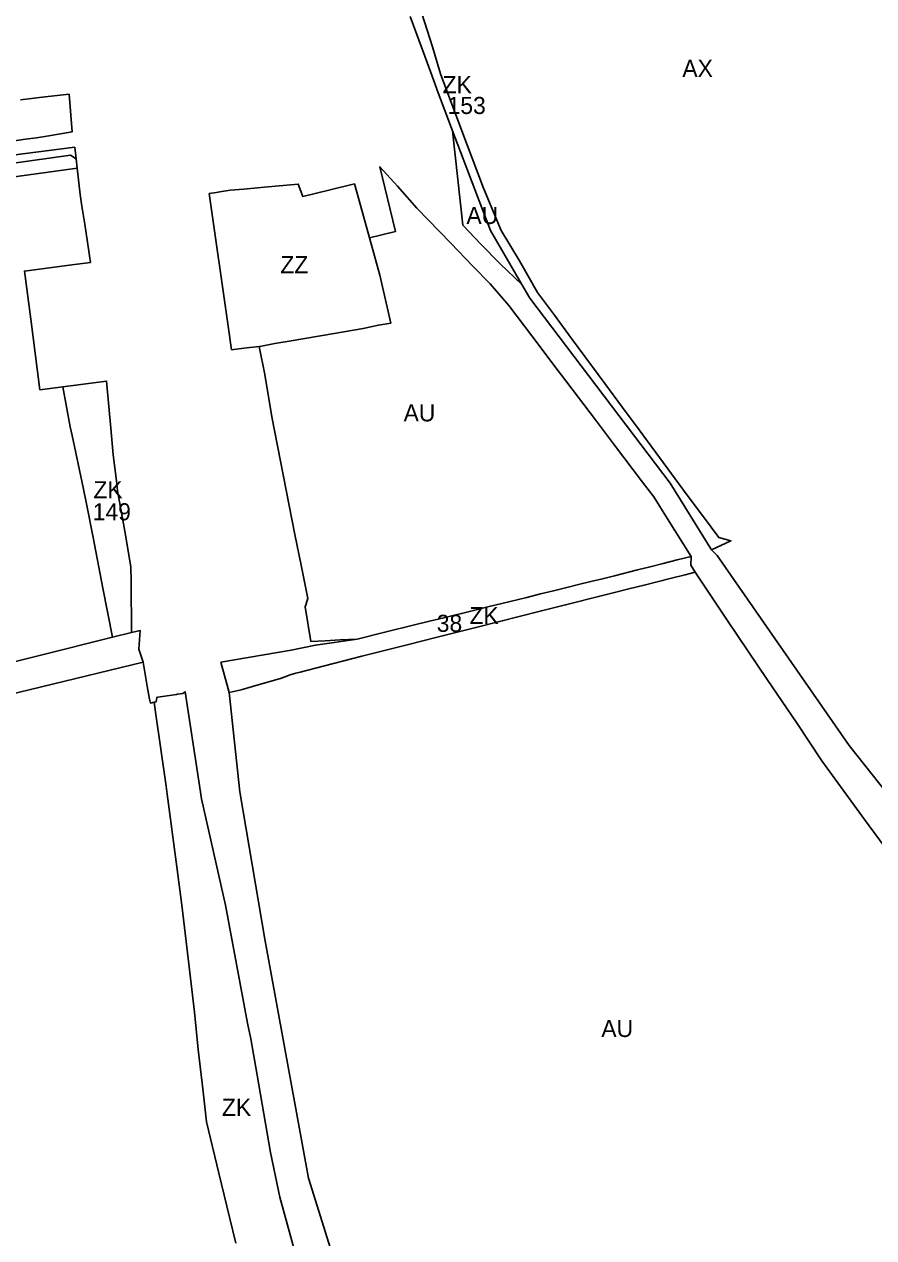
# Model space of a CAD drawing. Extents: x -521939 to -516426, y -1197857 to -1189551.
# Drawn here: x -519323 to -518826, y -1192859 to -1192149 of the extents above; entities that cross this region are included whole.
import ezdxf

# ---------------------------------------------------------------- set-up
doc = ezdxf.new("R2010")
doc.units = 0
for name, color, linetype in [('90640013', 7, 'Continuous'), ('90670013', 7, 'Continuous'), ('90710013', 7, 'Continuous'), ('90710023', 7, 'Continuous'), ('90750013', 7, 'Continuous'), ('90760013', 7, 'Continuous'), ('ID_navrh', 7, 'Continuous')]:
    doc.layers.add(name, color=color, linetype=linetype)

msp = doc.modelspace()

# ---------------------------------------------------------------- linework, layer by layer
at = {"layer": '90640013'}
msp.add_lwpolyline([(-519293.15, -1192221.23), (-519385.99, -1192233.14), (-519458.84, -1192240.98), (-519478.96, -1192243.26), (-519486.4, -1192244.11), (-519538.54, -1192250.02), (-519608.83, -1192258.36), (-519670.99, -1192265.56), (-519670.87, -1192266.69), (-519670.1, -1192273.68), (-519660.91, -1192268.23), (-519608.82, -1192261.75), (-519538.31, -1192254.24), (-519485.83, -1192249.1), (-519482.85, -1192248.8), (-519478.37, -1192248.37), (-519457.41, -1192246.31), (-519414.35, -1192241.81), (-519386.04, -1192238.58), (-519295.56, -1192225.98), (-519292.39, -1192228.11), (-519293.15, -1192221.23)], dxfattribs=at)
at = {"layer": '90670013'}
for points in [[(-519334.91, -1192218.48), (-519322.01, -1192216.62), (-519315.51, -1192215.67), (-519309.5, -1192214.8), (-519294.58, -1192212.21), (-519296.37, -1192190.24)], [(-519296.37, -1192190.24), (-519312.21, -1192192.03), (-519318.4, -1192192.73), (-519324.93, -1192193.46)], [(-519129.41, -1192242.66), (-519144.59, -1192246.35), (-519159.77, -1192250.04), (-519162.39, -1192242.78), (-519182.27, -1192244.61), (-519186.2, -1192244.97), (-519194.24, -1192245.71), (-519202.16, -1192246.44), (-519208.32, -1192247.41), (-519210.17, -1192247.71), (-519214.49, -1192248.39), (-519203.38, -1192325.77), (-519201.39, -1192339.64), (-519194.23, -1192338.74), (-519185.2, -1192337.66), (-519183.95, -1192337.51), (-519176.01, -1192336.03), (-519167.69, -1192334.62), (-519141.44, -1192330.1), (-519124.49, -1192327.18), (-519115.46, -1192325.17), (-519108.18, -1192324.09), (-519114.73, -1192296.08), (-519120.71, -1192274.22), (-519126.69, -1192252.35), (-519129.41, -1192242.66)]]:
    msp.add_lwpolyline(points, dxfattribs=at)
at = {"layer": '90710013'}
for points in [[(-519271.05, -1192507.61), (-519443.57, -1192550.97)], [(-519372.23, -1192551.03), (-519253.11, -1192522.25), (-519255.72, -1192514.6), (-519254.84, -1192503.78), (-519260.01, -1192504.83), (-519271.05, -1192507.61)], [(-519164.09, -1192868.23), (-519173.07, -1192834.93), (-519178.57, -1192808.82), (-519186.41, -1192763.61), (-519190.11, -1192742.39), (-519192.03, -1192733.27), (-519205.04, -1192664.2), (-519218.96, -1192602.21), (-519220.59, -1192591.78), (-519228.6, -1192539.54), (-519229.85, -1192540.57), (-519233.01, -1192541.03), (-519233.52, -1192541.1), (-519244.62, -1192542.72), (-519245.21, -1192542.95), (-519245.6, -1192545.49), (-519246.64, -1192545.7), (-519245.81, -1192551.56), (-519239.7, -1192594.73), (-519239.08, -1192599.36), (-519233.4, -1192641.79), (-519230.4, -1192664.21), (-519227.87, -1192685.59), (-519225.48, -1192707.05), (-519223.15, -1192726.84), (-519220.92, -1192748.67), (-519218.26, -1192771.67), (-519216.11, -1192790.93), (-519214.93, -1192795.79), (-519208.82, -1192820.97), (-519202.59, -1192846.65), (-519198.9, -1192861.88)]]:
    msp.add_lwpolyline(points, dxfattribs=at)
at = {"layer": '90710023'}
for points in [[(-519096.85, -1192144.75), (-519088.41, -1192167.96), (-519084.92, -1192177.56), (-519080.59, -1192189.45), (-519072.1, -1192211.71)], [(-519072.1, -1192211.71), (-519059.06, -1192245.89), (-519049.87, -1192269.96), (-519045.63, -1192277.25), (-519031.55, -1192301.49), (-519026.95, -1192309.4), (-518944.8, -1192417.71), (-518921.58, -1192455.03), (-518920.67, -1192456.5), (-518909.26, -1192451.23), (-518916.45, -1192449.41), (-518925.41, -1192437.29), (-518934.83, -1192424.56), (-518950.99, -1192402.69), (-518962.98, -1192386.51), (-518972.74, -1192373.31), (-518982.99, -1192359.44), (-519002.52, -1192333.06), (-519012.56, -1192319.48), (-519022.45, -1192306.15), (-519032.9, -1192287.75), (-519043.74, -1192269.98), (-519054.11, -1192245.13), (-519067.32, -1192210.12), (-519079.2, -1192178.33), (-519083.86, -1192162.62), (-519090.14, -1192143.06)], [(-519670.1, -1192273.68), (-519669.7, -1192277.39), (-519607.9, -1192269.69), (-519537.49, -1192262.2), (-519484.92, -1192257.05), (-519481.94, -1192256.7), (-519477.47, -1192256.17), (-519456.62, -1192254.15), (-519413.5, -1192249.64), (-519385.05, -1192246.39), (-519291.8, -1192233.4), (-519292.39, -1192228.11), (-519295.56, -1192225.98), (-519386.04, -1192238.58), (-519414.35, -1192241.81), (-519457.41, -1192246.31), (-519478.37, -1192248.37), (-519482.85, -1192248.8), (-519485.83, -1192249.1), (-519538.31, -1192254.24), (-519608.82, -1192261.75), (-519660.91, -1192268.23), (-519670.1, -1192273.68)], [(-519271.05, -1192507.61), (-519260.01, -1192504.83), (-519260.21, -1192475.38), (-519260.27, -1192466.51), (-519263.91, -1192445.66), (-519268.03, -1192422.01), (-519268.72, -1192416.34), (-519270.57, -1192401.05), (-519272, -1192385.55), (-519274.55, -1192357.98), (-519300.09, -1192361.31), (-519295.76, -1192384.75), (-519294.71, -1192389.71), (-519288.26, -1192420.08), (-519286.2, -1192429.76), (-519282.36, -1192449.47), (-519276.62, -1192479), (-519271.05, -1192507.61)], [(-519207.76, -1192522.22), (-519202.8, -1192540.04), (-519195.88, -1192538.48), (-519185.81, -1192535.58), (-519172.77, -1192531.87), (-519167.2, -1192529.66), (-519163.86, -1192528.76), (-519161.28, -1192528.12), (-519152.38, -1192525.82), (-519125.24, -1192518.78), (-519097.19, -1192511.77), (-519090.36, -1192509.99), (-519081.2, -1192507.68), (-519060.87, -1192502.57), (-519043.04, -1192498.09), (-519033.96, -1192495.77), (-519020.11, -1192492.23), (-519006, -1192488.76), (-518985.24, -1192483.53), (-518977.46, -1192481.59), (-518969.05, -1192479.46), (-518960.05, -1192477.14), (-518952.49, -1192475.3), (-518944.06, -1192473.16), (-518936.14, -1192471.19), (-518930.23, -1192469.72), (-518932.84, -1192465.6), (-518932.56, -1192460.45), (-518940.73, -1192462.51), (-518948.86, -1192464.56), (-518956.58, -1192466.5), (-518963.93, -1192468.35), (-518977.36, -1192471.72), (-518984.47, -1192473.47), (-518991.27, -1192475.14), (-518998.5, -1192476.92), (-519005.33, -1192478.6), (-519013.08, -1192480.51), (-519020.71, -1192482.38), (-519028.71, -1192484.35), (-519043.33, -1192487.95), (-519051.58, -1192489.98), (-519059.9, -1192492.02), (-519077.24, -1192496.29), (-519085.55, -1192498.33), (-519094.37, -1192500.5), (-519111.71, -1192504.77), (-519127.99, -1192508.77), (-519152.33, -1192512.23), (-519166.59, -1192515.29), (-519207.76, -1192522.22)]]:
    msp.add_lwpolyline(points, dxfattribs=at)
at = {"layer": '90750013'}
for points in [[(-519072.1, -1192211.71), (-519066.07, -1192266.75), (-519055.66, -1192277.84), (-519044.36, -1192289.47), (-519031.55, -1192301.49), (-519045.63, -1192277.25), (-519049.87, -1192269.96), (-519059.06, -1192245.89), (-519072.1, -1192211.71)], [(-518932.56, -1192460.45), (-518946.37, -1192438.53), (-518954.47, -1192425.68), (-518960.98, -1192417.09), (-518977.44, -1192395.36), (-518988.01, -1192381.41), (-519005.96, -1192357.71), (-519012.83, -1192348.64), (-519021.5, -1192337.2), (-519030.1, -1192325.84), (-519039.22, -1192313.8), (-519050.21, -1192301.17), (-519060.48, -1192290.5), (-519073.17, -1192277.32), (-519092.95, -1192256.78), (-519104.36, -1192244.08), (-519114.65, -1192232.63), (-519105.51, -1192270.55), (-519120.71, -1192274.22), (-519114.73, -1192296.08), (-519108.18, -1192324.09), (-519115.46, -1192325.17), (-519124.49, -1192327.18), (-519141.44, -1192330.1), (-519167.69, -1192334.62), (-519176.01, -1192336.03), (-519183.95, -1192337.51), (-519185.2, -1192337.66), (-519181.95, -1192354.19), (-519177.88, -1192378.92), (-519164.38, -1192447.68), (-519160.77, -1192465.6), (-519156.7, -1192485.01), (-519158.26, -1192489.84), (-519155.04, -1192510.13), (-519146.55, -1192509.71), (-519137.86, -1192509.27), (-519127.99, -1192508.77), (-519111.71, -1192504.77), (-519094.37, -1192500.5), (-519085.55, -1192498.33), (-519077.24, -1192496.29), (-519059.9, -1192492.02), (-519051.58, -1192489.98), (-519043.33, -1192487.95), (-519028.71, -1192484.35), (-519020.71, -1192482.38), (-519013.08, -1192480.51), (-519005.33, -1192478.6), (-518998.5, -1192476.92), (-518991.27, -1192475.14), (-518984.47, -1192473.47), (-518977.36, -1192471.72), (-518963.93, -1192468.35), (-518956.58, -1192466.5), (-518948.86, -1192464.56), (-518940.73, -1192462.51), (-518932.56, -1192460.45)], [(-518816.35, -1192634.29), (-518831.07, -1192614.22), (-518842.04, -1192599.23), (-518856.13, -1192579.88), (-518871, -1192557.6), (-518888.04, -1192532.35), (-518899.32, -1192515.59), (-518911.42, -1192497.6), (-518924.38, -1192478.48), (-518930.23, -1192469.72), (-518936.14, -1192471.19), (-518944.06, -1192473.16), (-518952.49, -1192475.3), (-518960.05, -1192477.14), (-518969.05, -1192479.46), (-518977.46, -1192481.59), (-518985.24, -1192483.53), (-519006, -1192488.76), (-519020.11, -1192492.23), (-519033.96, -1192495.77), (-519043.04, -1192498.09), (-519060.87, -1192502.57), (-519081.2, -1192507.68), (-519090.36, -1192509.99), (-519097.19, -1192511.77), (-519125.24, -1192518.78), (-519152.38, -1192525.82), (-519161.28, -1192528.12), (-519163.86, -1192528.76), (-519167.2, -1192529.66), (-519172.77, -1192531.87), (-519185.81, -1192535.58), (-519195.88, -1192538.48), (-519202.8, -1192540.04), (-519196.54, -1192598), (-519181.88, -1192684.13), (-519156.37, -1192823.91), (-519143.51, -1192865.04)]]:
    msp.add_lwpolyline(points, dxfattribs=at)
at = {"layer": '90760013'}
for points in [[(-519090.14, -1192143.06), (-519083.86, -1192162.62), (-519079.2, -1192178.33), (-519067.32, -1192210.12), (-519054.11, -1192245.13), (-519043.74, -1192269.98), (-519032.9, -1192287.75), (-519022.45, -1192306.15), (-519012.56, -1192319.48), (-519002.52, -1192333.06), (-518982.99, -1192359.44), (-518972.74, -1192373.31), (-518962.98, -1192386.51), (-518950.99, -1192402.69), (-518934.83, -1192424.56), (-518925.41, -1192437.29), (-518916.45, -1192449.41), (-518909.26, -1192451.23), (-518920.67, -1192456.5), (-518917.29, -1192459.81), (-518840.07, -1192570.95), (-518813.27, -1192604.88)], [(-519443.57, -1192550.97), (-519271.05, -1192507.61), (-519276.62, -1192479), (-519282.36, -1192449.47), (-519286.2, -1192429.76), (-519288.26, -1192420.08), (-519294.71, -1192389.71), (-519295.76, -1192384.75), (-519300.09, -1192361.31), (-519313.5, -1192363.06), (-519318.89, -1192321.77), (-519322.56, -1192293.65), (-519294.91, -1192290.05), (-519283.96, -1192288.62), (-519284.43, -1192284.69), (-519284.84, -1192282.04), (-519287.31, -1192266.22), (-519288.95, -1192255.73), (-519290, -1192248.98), (-519291.8, -1192233.4), (-519385.05, -1192246.39)], [(-519198.9, -1192861.88), (-519202.59, -1192846.65), (-519208.82, -1192820.97), (-519214.93, -1192795.79), (-519216.11, -1192790.93), (-519218.26, -1192771.67), (-519220.92, -1192748.67), (-519223.15, -1192726.84), (-519225.48, -1192707.05), (-519227.87, -1192685.59), (-519230.4, -1192664.21), (-519233.4, -1192641.79), (-519239.08, -1192599.36), (-519239.7, -1192594.73), (-519245.81, -1192551.56), (-519246.64, -1192545.7), (-519248.82, -1192546.17), (-519249.45, -1192543.81), (-519250.78, -1192536.34), (-519253.11, -1192522.25), (-519372.23, -1192551.03)]]:
    msp.add_lwpolyline(points, dxfattribs=at)

# ---------------------------------------------------------------- texts
at = {"layer": '90670013'}
msp.add_text('ZZ', height=10, rotation=360, dxfattribs=at).set_placement((-519172.85, -1192294.9))
at = {"layer": '90710013'}
msp.add_text('ZK', height=10, dxfattribs=at).set_placement((-519207.03, -1192787.44))
at = {"layer": '90710023'}
for p in [(-519077.96, -1192189.68), (-519282.2, -1192426.48), (-519062.21, -1192499.97)]:
    msp.add_text('ZK', height=10, rotation=360, dxfattribs=at).set_placement(p)
at = {"layer": '90750013'}
for rotation, p in [(0, (-519064.02, -1192266.11)), (360, (-519100.75, -1192381.51)), (0, (-518985.09, -1192741.35))]:
    msp.add_text('AU', height=10, rotation=rotation, dxfattribs=at).set_placement(p)
at = {"layer": '90760013'}
msp.add_text('AX', height=10, rotation=360, dxfattribs=at).set_placement((-518937.7, -1192180.15))
at = {"layer": 'ID_navrh'}
for s, p in [('153', (-519075.02, -1192201.83)), ('149', (-519282.6, -1192439.34)), ('38', (-519081.35, -1192504.55))]:
    msp.add_text(s, height=10, rotation=0, dxfattribs=at).set_placement(p)

doc.saveas('drawing.dxf')
